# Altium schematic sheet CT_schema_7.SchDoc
size 146 x 119 mm
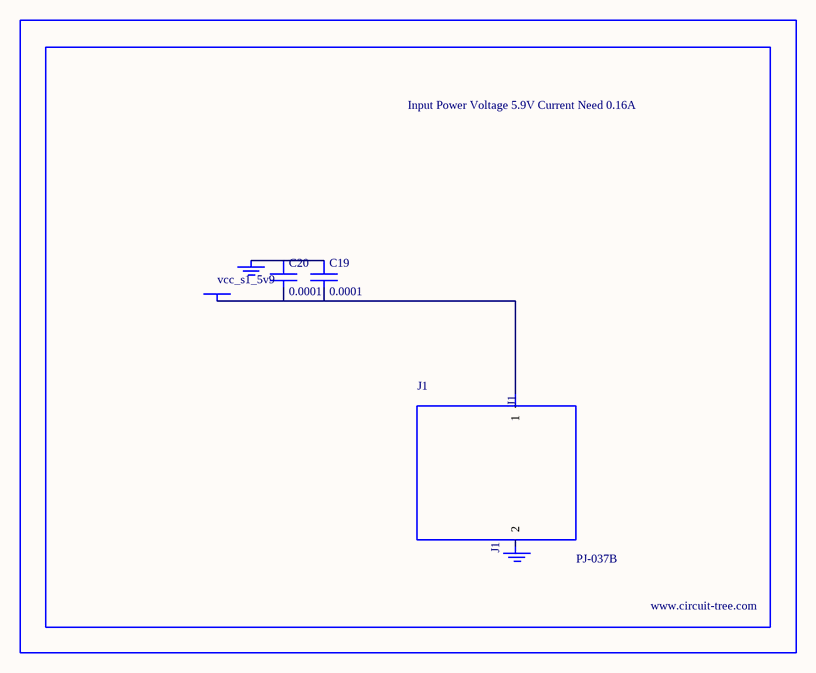
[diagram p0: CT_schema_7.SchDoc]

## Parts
BORDER6  (no value)
C19  0.0001  [EXV-9H]
C20  0.0001  [EXV-9H]
GND_INSTANCE_6_0  (no value)
GND_INSTANCE_6_1  (no value)
J1  PJ-037B  [PJ-037B_PACKAGE]
POWER_INSTANCE_6_0  vcc_s1_5v9

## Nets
NetC19_1: C19.1 C20.1 GND_INSTANCE_6_0.0(GND)
NetC19_2: C19.2 C20.2 J1.1 POWER_INSTANCE_6_0.0(PWR)

Not connected (* = marked no-connect by the designer): GND_INSTANCE_6_1 0(GND); J1 2

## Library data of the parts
BORDER6 = BORDER_PAGE6
C19 C20 = EDK107M035A9HAA
GND_INSTANCE_6_0 GND_INSTANCE_6_1 = GND
POWER_INSTANCE_6_0 = PWR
